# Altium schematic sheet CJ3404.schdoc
size 127 x 101 mm
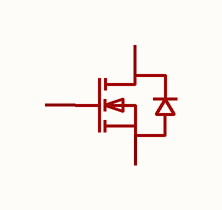
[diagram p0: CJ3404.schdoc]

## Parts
Q?  cj3404  [SOT-23-3_L2.9-W1.3-P1.90-LS2.4-BR]  (value not drawn)

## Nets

Not connected (* = marked no-connect by the designer): Q? 1(G) 2(S) 3(D)

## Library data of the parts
Q? = cj3404: 数量:1个N沟道;漏源电压(Vdss):30V;连续漏极电流(Id):5.8A;导通电阻(RDS(on)):30mΩ@10V;耗散功率(Pd):-;阈值电压(Vgs(th)):1V;; Manufacturer: CJ(江苏长电/长晶); AddInBom: yes; ModelId: c62791f0466c4ae2a892c056b845b0ca; ModelName: SOT-23-3P_L2.9-W1.3-H1.0-LS2.4-P0.95; ModelTransform: 98.425,114.173,0,180,0,0,0.0005,-0.0005,0; Number: 1个N沟道; Drain to Source Voltage: 30V; Current - Continuous Drain(Id): 5.8A; Gate Threshold Voltage (Vgs(th)): 1V; Input Capacitance(Ciss): 820pF; Reverse Transfer Capacitance (Crss@Vds): 85pF; Type: N沟道; Output Capacitance(Coss): 118pF; Vgs: ±20V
